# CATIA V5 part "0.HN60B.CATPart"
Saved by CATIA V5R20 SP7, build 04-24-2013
Part number: 0.HN60B
Material "Nessuno"
Bounding box of the stored display mesh (mm): x 0 to 149.213, y -124.685 to 0, z -56.919 to 41.584
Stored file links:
  C:\Users\designer2\Desktop\Ottobre 2022\25-10-2022\04\Yori Evo 48V\0.HN60B.CATPart
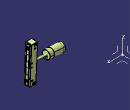
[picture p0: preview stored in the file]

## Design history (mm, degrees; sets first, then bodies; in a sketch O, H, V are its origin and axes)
AxisSystem1: origin (0, 0, 0), X (1, 0, 0), Y (0, 1, 0), Z (0, 0, 1)
Set1
  DatumSurface1
Body1 (main body), material "Nessuno"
